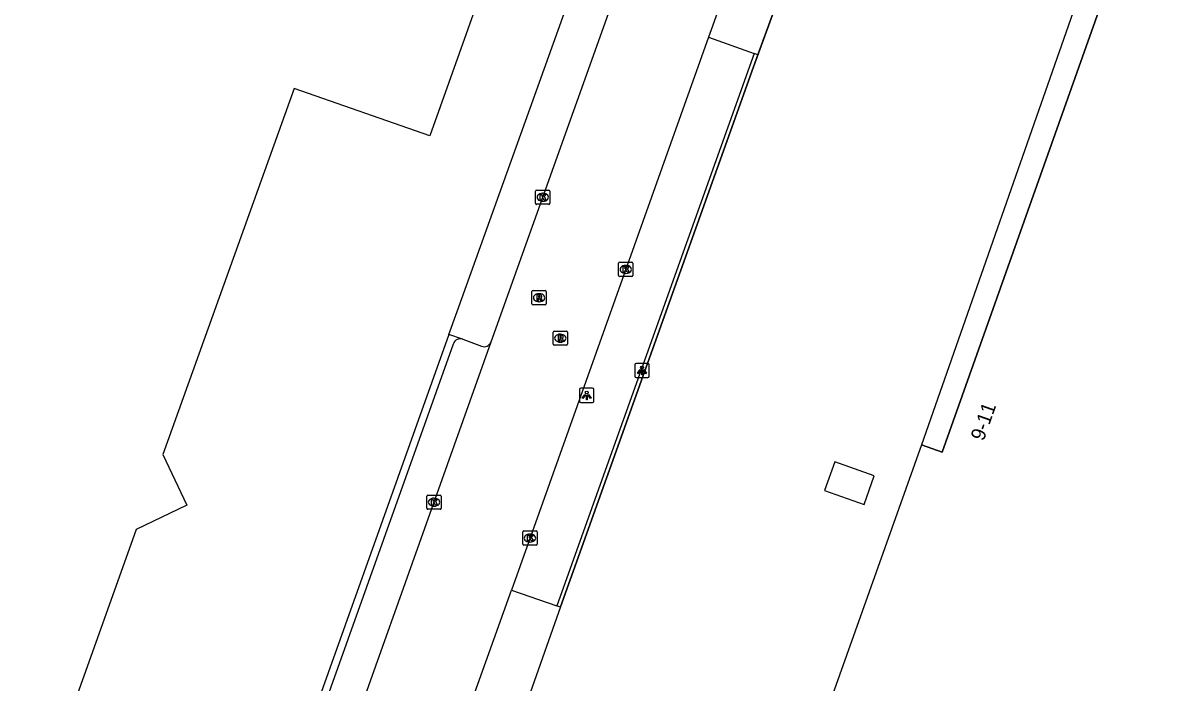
# Model space of a CAD drawing. Extents: x 155018 to 156648, y 383980 to 385733.
# Drawn here: x 155664.5 to 155745.3, y 384932.5 to 384978.8 of the extents above; entities that cross this region are included whole.
import ezdxf

# ---------------------------------------------------------------- set-up
doc = ezdxf.new("R2010")
doc.units = 0
for name, color, linetype in [('IMGEO_Groenvoorziening', 7, 'Continuous'), ('IMGEO_Hek', 7, 'Continuous'), ('IMGEO_Kolk', 7, 'Continuous'), ('IMGEO_Lage_trafo', 7, 'Continuous'), ('IMGEO_Lichtpunt', 7, 'Continuous'), ('IMGEO_Pand', 7, 'Continuous'), ('IMGEO_Pand_nummerreeks', 7, 'Continuous'), ('IMGEO_Pand_overbouw', 7, 'Continuous'), ('IMGEO_Rijbaan_lokaal_gesloten', 7, 'Continuous'), ('IMGEO_Rioolput', 7, 'Continuous'), ('IMGEO_Voetpad_open', 7, 'Continuous')]:
    doc.layers.add(name, color=color, linetype=linetype)

msp = doc.modelspace()

# ---------------------------------------------------------------- linework, layer by layer
at = {"layer": 'IMGEO_Groenvoorziening'}
msp.add_lwpolyline([(155702.172, 384937.868), (155702.844, 384939.771), (155715.7, 384975.738), (155716.009, 384976.585)], dxfattribs=at)
at = {"layer": 'IMGEO_Hek'}
for points in [[(155724.402, 385000), (155719.139, 384985.171), (155715.7, 384975.738), (155702.844, 384939.771), (155702.172, 384937.868)], [(155702.172, 384937.868), (155696.786, 384922.628)]]:
    msp.add_lwpolyline(points, dxfattribs=at)
at = {"layer": 'IMGEO_Kolk'}
for p, q in [((155700.418, 384966.171), (155700.418, 384967.023)), ((155700.493, 384967.097), (155701.345, 384967.097)), ((155700.906, 384966.877), (155700.931, 384966.877)), ((155701.419, 384967.023), (155701.419, 384966.171)), ((155701.345, 384966.097), (155700.493, 384966.097)), ((155700.929, 384966.317), (155700.904, 384966.317)), ((155706.238, 384961.108), (155706.238, 384961.96)), ((155706.313, 384962.034), (155707.165, 384962.034)), ((155707.239, 384961.96), (155707.239, 384961.108)), ((155706.749, 384961.254), (155706.724, 384961.254)), ((155706.726, 384961.814), (155706.751, 384961.814)), ((155707.165, 384961.034), (155706.313, 384961.034)), ((155692.796, 384944.78), (155692.796, 384945.632)), ((155692.871, 384945.706), (155693.723, 384945.706)), ((155693.307, 384944.926), (155693.282, 384944.926)), ((155693.284, 384945.486), (155693.309, 384945.486)), ((155693.797, 384945.632), (155693.797, 384944.78)), ((155693.723, 384944.706), (155692.871, 384944.706)), ((155699.522, 384942.263), (155699.522, 384943.115)), ((155699.597, 384943.189), (155700.449, 384943.189)), ((155700.01, 384942.969), (155700.035, 384942.969)), ((155700.523, 384943.115), (155700.523, 384942.263)), ((155700.449, 384942.189), (155699.597, 384942.189)), ((155700.033, 384942.409), (155700.008, 384942.409))]:
    msp.add_line(p, q, dxfattribs=at)
for points in [[(155700.418, 384966.171), (155700.418, 384967.023)], [(155700.493, 384967.097), (155701.345, 384967.097)], [(155700.739, 384966.797), (155700.862, 384966.797), (155700.862, 384966.646), (155700.992, 384966.797), (155701.156, 384966.797), (155701.01, 384966.646), (155701.163, 384966.397), (155701.011, 384966.397), (155700.926, 384966.561), (155700.862, 384966.494), (155700.862, 384966.397), (155700.739, 384966.397), (155700.739, 384966.797)], [(155701.419, 384967.023), (155701.419, 384966.171)], [(155701.345, 384966.097), (155700.493, 384966.097)], [(155706.238, 384961.108), (155706.238, 384961.96)], [(155706.313, 384962.034), (155707.165, 384962.034)], [(155707.239, 384961.96), (155707.239, 384961.108)], [(155706.559, 384961.734), (155706.682, 384961.734), (155706.682, 384961.583), (155706.812, 384961.734), (155706.976, 384961.734), (155706.83, 384961.583), (155706.983, 384961.334), (155706.831, 384961.334), (155706.746, 384961.498), (155706.682, 384961.431), (155706.682, 384961.334), (155706.559, 384961.334), (155706.559, 384961.734)], [(155707.165, 384961.034), (155706.313, 384961.034)], [(155692.796, 384944.78), (155692.796, 384945.632)], [(155692.871, 384945.706), (155693.723, 384945.706)], [(155693.117, 384945.406), (155693.24, 384945.406), (155693.24, 384945.255), (155693.37, 384945.406), (155693.534, 384945.406), (155693.388, 384945.255), (155693.541, 384945.006), (155693.389, 384945.006), (155693.304, 384945.17), (155693.24, 384945.103), (155693.24, 384945.006), (155693.117, 384945.006), (155693.117, 384945.406)], [(155693.797, 384945.632), (155693.797, 384944.78)], [(155693.723, 384944.706), (155692.871, 384944.706)], [(155699.522, 384942.263), (155699.522, 384943.115)], [(155699.597, 384943.189), (155700.449, 384943.189)], [(155699.843, 384942.889), (155699.966, 384942.889), (155699.966, 384942.738), (155700.096, 384942.889), (155700.26, 384942.889), (155700.114, 384942.738), (155700.267, 384942.489), (155700.115, 384942.489), (155700.03, 384942.653), (155699.966, 384942.586), (155699.966, 384942.489), (155699.843, 384942.489), (155699.843, 384942.889)], [(155700.523, 384943.115), (155700.523, 384942.263)], [(155700.449, 384942.189), (155699.597, 384942.189)]]:
    msp.add_lwpolyline(points, dxfattribs=at)
for centre, start, end in [((155700.495, 384967.021), 91.55205, 178.44795), ((155700.495, 384967.021), 91.55205, 178.44795), ((155701.343, 384967.021), 1.55205, 88.44795), ((155701.343, 384967.021), 1.55205, 88.44795), ((155700.495, 384966.173), 181.55205, 268.44795), ((155700.495, 384966.173), 181.55205, 268.44795), ((155701.343, 384966.173), 271.55205, 358.44795), ((155701.343, 384966.173), 271.55205, 358.44795), ((155706.315, 384961.958), 91.55205, 178.44795), ((155706.315, 384961.958), 91.55205, 178.44795), ((155707.163, 384961.958), 1.55205, 88.44795), ((155707.163, 384961.958), 1.55205, 88.44795), ((155706.315, 384961.11), 181.55205, 268.44795), ((155706.315, 384961.11), 181.55205, 268.44795), ((155707.163, 384961.11), 271.55205, 358.44795), ((155707.163, 384961.11), 271.55205, 358.44795), ((155692.873, 384945.63), 91.55205, 178.44795), ((155692.873, 384945.63), 91.55205, 178.44795), ((155693.721, 384945.63), 1.55205, 88.44795), ((155693.721, 384945.63), 1.55205, 88.44795), ((155692.873, 384944.782), 181.55205, 268.44795), ((155692.873, 384944.782), 181.55205, 268.44795), ((155693.721, 384944.782), 271.55205, 358.44795), ((155693.721, 384944.782), 271.55205, 358.44795), ((155699.599, 384943.113), 91.55205, 178.44795), ((155699.599, 384943.113), 91.55205, 178.44795), ((155700.447, 384943.113), 1.55205, 88.44795), ((155700.447, 384943.113), 1.55205, 88.44795), ((155699.599, 384942.265), 181.55205, 268.44795), ((155699.599, 384942.265), 181.55205, 268.44795), ((155700.447, 384942.265), 271.55205, 358.44795), ((155700.447, 384942.265), 271.55205, 358.44795)]:
    msp.add_arc(centre, 0.0765, start, end, dxfattribs=at)
for centre, major_axis, ratio, start_param, end_param in [((155700.905, 384966.597), (-0.387, 0.002), 0.722429, 4.712389, 7.853982), ((155700.93, 384966.597), (-0.39, 0.002), 0.717154, 1.570796, 4.712389), ((155706.725, 384961.534), (-0.387, 0.002), 0.722429, 4.712389, 7.853982), ((155706.75, 384961.534), (-0.39, 0.002), 0.717154, 1.570796, 4.712389), ((155693.283, 384945.206), (-0.387, 0.002), 0.722429, 4.712389, 7.853982), ((155693.308, 384945.206), (-0.39, 0.002), 0.717154, 1.570796, 4.712389), ((155700.009, 384942.689), (-0.387, 0.002), 0.722429, 4.712389, 7.853982), ((155700.034, 384942.689), (-0.39, 0.002), 0.717154, 1.570796, 4.712389)]:
    msp.add_ellipse(centre, major_axis=major_axis, ratio=ratio, start_param=start_param, end_param=end_param, dxfattribs=at)
at = {"layer": 'IMGEO_Lage_trafo'}
msp.add_lwpolyline([(155724.161, 384947.053), (155721.388, 384948.045), (155720.674, 384946.023), (155723.451, 384945.042), (155724.161, 384947.053)], dxfattribs=at)
at = {"layer": 'IMGEO_Lichtpunt'}
for p, q in [((155707.383, 384954.844), (155707.383, 384954.037)), ((155707.383, 384954.844), (155707.383, 384954.037)), ((155708.285, 384954.939), (155707.477, 384954.939)), ((155708.285, 384954.939), (155707.477, 384954.939)), ((155708.379, 384954.037), (155708.379, 384954.844)), ((155708.379, 384954.037), (155708.379, 384954.844)), ((155707.477, 384953.943), (155708.285, 384953.943)), ((155707.477, 384953.943), (155708.285, 384953.943)), ((155703.503, 384953.102), (155703.503, 384952.295)), ((155703.503, 384953.102), (155703.503, 384952.295)), ((155704.405, 384953.197), (155703.597, 384953.197)), ((155704.405, 384953.197), (155703.597, 384953.197)), ((155704.499, 384952.295), (155704.499, 384953.102)), ((155704.499, 384952.295), (155704.499, 384953.102)), ((155703.597, 384952.201), (155704.405, 384952.201)), ((155703.597, 384952.201), (155704.405, 384952.201))]:
    msp.add_line(p, q, dxfattribs=at)
for points in [[(155707.757, 384954.508), (155707.796, 384954.48), (155707.608, 384954.218), (155707.57, 384954.245), (155707.757, 384954.508)], [(155707.859, 384954.46), (155707.906, 384954.46), (155707.906, 384954.138), (155707.859, 384954.138), (155707.859, 384954.46)], [(155707.969, 384954.48), (155708.007, 384954.507), (155708.194, 384954.245), (155708.155, 384954.217), (155707.969, 384954.48)], [(155703.877, 384952.766), (155703.916, 384952.738), (155703.728, 384952.476), (155703.69, 384952.503), (155703.877, 384952.766)], [(155703.979, 384952.718), (155704.026, 384952.718), (155704.026, 384952.396), (155703.979, 384952.396), (155703.979, 384952.718)], [(155704.089, 384952.738), (155704.127, 384952.765), (155704.314, 384952.503), (155704.275, 384952.475), (155704.089, 384952.738)]]:
    msp.add_lwpolyline(points, dxfattribs=at)
for centre in [(155707.882, 384954.642), (155704.002, 384952.9)]:
    msp.add_circle(centre, 0.0994, dxfattribs=at)
for centre, start, end in [((155707.477, 384954.844), 90, 180), ((155707.477, 384954.844), 90, 180), ((155708.285, 384954.844), 0, 90), ((155708.285, 384954.844), 0, 90), ((155707.477, 384954.037), 180, 270), ((155707.477, 384954.037), 180, 270), ((155708.285, 384954.037), 270, 0), ((155708.285, 384954.037), 270, 360), ((155703.597, 384953.102), 90, 180), ((155703.597, 384953.102), 90, 180), ((155704.405, 384953.102), 0, 90), ((155704.405, 384953.102), 0, 90), ((155703.597, 384952.295), 180, 270), ((155703.597, 384952.295), 180, 270), ((155704.405, 384952.295), 270, 0), ((155704.405, 384952.295), 270, 360)]:
    msp.add_arc(centre, 0.0946, start, end, dxfattribs=at)
at = {"layer": 'IMGEO_Pand'}
for points in [[(155762.359, 385042.817), (155753.183, 385017.001), (155750.623, 385009.797), (155749.138, 385010.33), (155747.33, 385005.279), (155748.837, 385004.772), (155746.303, 384997.642), (155740.174, 384980.395), (155728.915, 384948.717), (155727.468, 384949.235), (155696.765, 384862.93), (155766.348, 384838.189), (155767.038, 384840.129), (155767.438, 384839.985), (155765.854, 384835.53), (155771.729, 384833.45), (155773.299, 384837.894), (155819.22, 384821.585), (155822.731, 384820.338), (155823.528, 384820.055), (155825.201, 384824.767), (155840.068, 384866.636)], [(155696.4, 384980.41), (155693.01, 384970.89), (155683.48, 384974.23), (155674.29, 384948.56), (155675.96, 384945), (155672.41, 384943.28), (155663.21, 384917.49)]]:
    msp.add_lwpolyline(points, dxfattribs=at)
at = {"layer": 'IMGEO_Pand_overbouw'}
msp.add_lwpolyline([(155738.587, 384980.964), (155727.468, 384949.235), (155728.915, 384948.717), (155740.174, 384980.395)], close=True, dxfattribs=at)
at = {"layer": 'IMGEO_Rijbaan_lokaal_gesloten'}
for points in [[(155711.66, 384996.694), (155697.277, 384956.434)], [(155715.089, 384984.941), (155712.738, 384978.347), (155712.551, 384977.822)], [(155712.551, 384977.822), (155698.719, 384939.029)], [(155697.277, 384956.434), (155683.176, 384916.819)], [(155693.322, 384923.959), (155698.719, 384939.029)]]:
    msp.add_lwpolyline(points, dxfattribs=at)
at = {"layer": 'IMGEO_Rioolput'}
for p, q in [((155700.163, 384959.121), (155700.163, 384959.973)), ((155700.238, 384960.047), (155701.09, 384960.047)), ((155700.651, 384959.827), (155700.676, 384959.827)), ((155701.164, 384959.973), (155701.164, 384959.121)), ((155701.09, 384959.047), (155700.238, 384959.047)), ((155700.674, 384959.267), (155700.649, 384959.267)), ((155701.652, 384956.283), (155701.652, 384957.135)), ((155701.727, 384957.209), (155702.579, 384957.209)), ((155702.653, 384957.135), (155702.653, 384956.283)), ((155702.163, 384956.429), (155702.138, 384956.429)), ((155702.14, 384956.989), (155702.165, 384956.989)), ((155702.579, 384956.209), (155701.727, 384956.209))]:
    msp.add_line(p, q, dxfattribs=at)
for points in [[(155700.163, 384959.121), (155700.163, 384959.973)], [(155700.238, 384960.047), (155701.09, 384960.047)], [(155700.752, 384959.745), (155700.5, 384959.747), (155700.5, 384959.347)], [(155700.5, 384959.347), (155700.624, 384959.347), (155700.624, 384959.509), (155700.635, 384959.509)], [(155700.678, 384959.666), (155700.624, 384959.666), (155700.624, 384959.585)], [(155700.624, 384959.585), (155700.676, 384959.585)], [(155700.682, 384959.48), (155700.753, 384959.347), (155700.893, 384959.347), (155700.828, 384959.473)], [(155701.164, 384959.973), (155701.164, 384959.121)], [(155701.09, 384959.047), (155700.238, 384959.047)], [(155701.652, 384956.283), (155701.652, 384957.135)], [(155701.727, 384957.209), (155702.579, 384957.209)], [(155702.653, 384957.135), (155702.653, 384956.283)], [(155702.241, 384956.907), (155701.989, 384956.909), (155701.989, 384956.509)], [(155701.989, 384956.509), (155702.113, 384956.509), (155702.113, 384956.671), (155702.124, 384956.671)], [(155702.167, 384956.828), (155702.113, 384956.828), (155702.113, 384956.747)], [(155702.113, 384956.747), (155702.165, 384956.747)], [(155702.171, 384956.642), (155702.242, 384956.509), (155702.382, 384956.509), (155702.317, 384956.635)], [(155702.579, 384956.209), (155701.727, 384956.209)]]:
    msp.add_lwpolyline(points, dxfattribs=at)
for centre, radius, start, end in [((155700.24, 384959.971), 0.0765, 91.55205, 178.44795), ((155700.24, 384959.971), 0.0765, 91.55205, 178.44795), ((155700.634, 384959.456), 0.0533, 26.02933, 88.69889), ((155700.66, 384959.774), 0.19, 274.7715, 282.96867), ((155700.684, 384959.57), 0.0964, 77.00612, 93.18647), ((155700.698, 384959.627), 0.0378, 276.66336, 79.67722), ((155700.751, 384959.635), 0.109, 350.36119, 89.41601), ((155700.749, 384959.635), 0.112, 277.58423, 350.98172), ((155700.733, 384959.42), 0.108, 29.51342, 73.79051), ((155701.088, 384959.971), 0.0765, 1.55205, 88.44795), ((155701.088, 384959.971), 0.0765, 1.55205, 88.44795), ((155700.24, 384959.123), 0.0765, 181.55205, 268.44795), ((155700.24, 384959.123), 0.0765, 181.55205, 268.44795), ((155701.088, 384959.123), 0.0765, 271.55205, 358.44795), ((155701.088, 384959.123), 0.0765, 271.55205, 358.44795), ((155701.729, 384957.133), 0.0765, 91.55205, 178.44795), ((155701.729, 384957.133), 0.0765, 91.55205, 178.44795), ((155702.577, 384957.133), 0.0765, 1.55205, 88.44795), ((155702.577, 384957.133), 0.0765, 1.55205, 88.44795), ((155701.729, 384956.285), 0.0765, 181.55205, 268.44795), ((155701.729, 384956.285), 0.0765, 181.55205, 268.44795), ((155702.123, 384956.618), 0.0533, 26.02933, 88.69889), ((155702.149, 384956.936), 0.19, 274.7715, 282.96867), ((155702.173, 384956.732), 0.0964, 77.00612, 93.18647), ((155702.187, 384956.789), 0.0378, 276.66336, 79.67722), ((155702.24, 384956.797), 0.109, 350.36119, 89.41601), ((155702.238, 384956.797), 0.112, 277.58423, 350.98172), ((155702.222, 384956.582), 0.108, 29.51342, 73.79051), ((155702.577, 384956.285), 0.0765, 271.55205, 358.44795), ((155702.577, 384956.285), 0.0765, 271.55205, 358.44795)]:
    msp.add_arc(centre, radius, start, end, dxfattribs=at)
for centre, major_axis, ratio, start_param, end_param in [((155700.65, 384959.547), (-0.387, 0.002), 0.722429, 4.712389, 7.853982), ((155700.675, 384959.547), (-0.39, 0.002), 0.717154, 1.570796, 4.712389), ((155702.139, 384956.709), (-0.387, 0.002), 0.722429, 4.712389, 7.853982), ((155702.164, 384956.709), (-0.39, 0.002), 0.717154, 1.570796, 4.712389)]:
    msp.add_ellipse(centre, major_axis=major_axis, ratio=ratio, start_param=start_param, end_param=end_param, dxfattribs=at)
at = {"layer": 'IMGEO_Voetpad_open'}
for points in [[(155694.342, 384956.978), (155694.915, 384958.585), (155709.077, 384998.076)], [(155716.009, 384976.585), (155718.598, 384983.687)], [(155712.551, 384977.822), (155715.734, 384976.686)], [(155715.734, 384976.686), (155701.902, 384937.934)], [(155716.009, 384976.585), (155715.734, 384976.686)], [(155694.342, 384956.978), (155670.262, 384889.44)], [(155681.192, 384918.565), (155694.651, 384956.324)], [(155695.309, 384956.629), (155695.291, 384956.637), (155694.342, 384956.978)], [(155695.309, 384956.629), (155696.632, 384956.139)], [(155698.719, 384939.029), (155701.902, 384937.934)], [(155702.172, 384937.868), (155696.786, 384922.628)], [(155701.902, 384937.934), (155702.172, 384937.868)]]:
    msp.add_lwpolyline(points, dxfattribs=at)
for centre, radius, start, end in [((155695.13, 384956.152), 0.509, 69.47559, 160.26229), ((155696.804, 384956.616), 0.507, 250.17, 338.98533)]:
    msp.add_arc(centre, radius, start, end, dxfattribs=at)

# ---------------------------------------------------------------- texts
at = {"layer": 'IMGEO_Pand_nummerreeks'}
msp.add_text('9-11', height=1, rotation=70.4337, dxfattribs=at).set_placement((155731.829, 384949.452))

doc.saveas('drawing.dxf')
